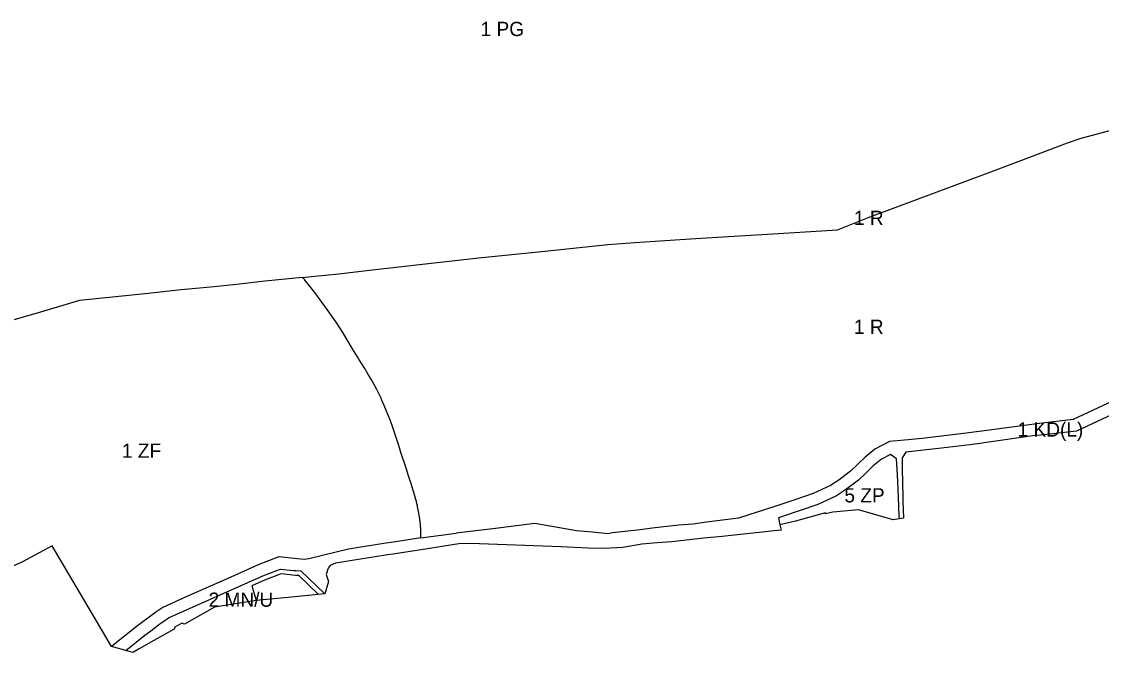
# Model space of a CAD drawing. Extents: x -286517 to -284367, y 35407 to 36486.
# Drawn here: x -286009 to -285100, y 35407 to 35938 of the extents above; entities that cross this region are included whole.
import ezdxf

# ---------------------------------------------------------------- set-up
doc = ezdxf.new("R2010")
doc.units = 0
for name, color, linetype in [('linie_rozgraniczajace', 7, 'Continuous'), ('linie_zabudowy_nieprzekraczalne', 7, 'Continuous'), ('oznaczenia_przeznaczen', 7, 'Continuous')]:
    doc.layers.add(name, color=color, linetype=linetype)

msp = doc.modelspace()

# ---------------------------------------------------------------- linework, layer by layer
at = {"layer": 'linie_rozgraniczajace'}
for p, q in [((-285772.1, 35722.75), (-285764.7, 35723.49)), ((-285672.47, 35503.54), (-285642.78, 35507.44))]:
    msp.add_line(p, q, dxfattribs=at)
for points in [[(-285764.7, 35723.49), (-285741.57, 35725.73), (-285715.72, 35728.86), (-285658.89, 35735.31), (-285621.32, 35739.63), (-285573.46, 35744.26), (-285515.27, 35750.49), (-285492.27, 35752.09), (-285441.45, 35755.6), (-285399.47, 35758.16), (-285371.51, 35759.76), (-285321.66, 35762.93), (-285296.42, 35772.95), (-285254.54, 35788.6), (-285197.18, 35810.16), (-285168.95, 35820.61), (-285128.18, 35836.27), (-285116.73, 35840.13), (-285060.82, 35855.07)], [(-285772.1, 35722.75), (-285804.01, 35719.56), (-285825.36, 35717.05), (-285846.68, 35714.99), (-285874.36, 35712.38), (-285902.1, 35709.3), (-285932.13, 35706.31), (-285959.96, 35703.43), (-285992.66, 35693.54), (-286021.94, 35685.16), (-286031.65, 35682.39)], [(-285672.47, 35503.54), (-285672.59, 35509.85), (-285672.95, 35514.75), (-285673.68, 35521.09), (-285674.72, 35527.12), (-285675.26, 35529.56), (-285675.49, 35530.6), (-285675.85, 35532.05), (-285676.33, 35533.99), (-285676.76, 35535.69), (-285677.61, 35538.8), (-285677.67, 35539.02), (-285679.81, 35546.07), (-285680.82, 35549.23), (-285681.53, 35551.43), (-285682.9, 35555.71), (-285684.97, 35562.13), (-285686.35, 35566.41), (-285687.89, 35571.22), (-285689.28, 35575.5), (-285691.19, 35581.36), (-285693.62, 35588.83), (-285696.05, 35596.3), (-285698.04, 35602.09), (-285701.36, 35610.08), (-285703.47, 35615.05), (-285705.62, 35620.11), (-285706, 35621), (-285707.39, 35624.07), (-285707.55, 35624.4), (-285708.96, 35627.23), (-285709.67, 35628.55), (-285713.15, 35635.07), (-285714.43, 35637.21), (-285717.13, 35641.69), (-285719.83, 35646.06), (-285724.7, 35653.92), (-285726.02, 35656.04), (-285730.11, 35662.65), (-285738.35, 35676.33), (-285743.26, 35684.15), (-285751.36, 35695.85), (-285761.83, 35710.13), (-285767.55, 35717.14), (-285770.26, 35720.58), (-285770.35, 35720.7), (-285772.1, 35722.75)], [(-285007.3, 35657.23), (-285123.28, 35603.1), (-285151.85, 35599.91), (-285200.22, 35593.46), (-285215.84, 35591.28), (-285250.46, 35587.29), (-285265.3, 35585.66), (-285278.05, 35584.62), (-285290.41, 35578.15), (-285298.47, 35571.48), (-285304.29, 35565.77), (-285310.72, 35559.57), (-285315.6, 35555.89), (-285320.66, 35552.08), (-285327.59, 35547.66), (-285342.17, 35540.82), (-285356.83, 35535.9), (-285374.6, 35529.96), (-285405.26, 35520.01), (-285414.23, 35518.91), (-285432.06, 35516.64), (-285443.44, 35515.15), (-285455.29, 35514.13), (-285465.42, 35512.98), (-285477.95, 35511.55), (-285487.83, 35510.37), (-285511.1, 35507.6), (-285515.26, 35506.97), (-285528.12, 35508.26), (-285541.4, 35509.47), (-285576.54, 35515.7), (-285609.77, 35511.46), (-285642.78, 35507.44)], [(-285038.41, 35631.83), (-285120.53, 35593.35), (-285150.63, 35589.98), (-285155.29, 35589.65), (-285198.44, 35583.61), (-285200, 35583.25), (-285201.51, 35582.91), (-285204.21, 35582.59), (-285210.29, 35581.87), (-285234.35, 35579.01), (-285264.34, 35575.7), (-285267.36, 35570.78), (-285267.31, 35562.03), (-285266.74, 35537.7), (-285266.71, 35534.18), (-285266.46, 35527.33), (-285266.33, 35520.07), (-285269.72, 35519.57), (-285275, 35518.8), (-285304.07, 35527.12), (-285325.73, 35525.21), (-285331.79, 35523.73), (-285331.99, 35524.52), (-285357.24, 35517.65), (-285370.29, 35514.52), (-285369.34, 35509.92), (-285375.26, 35509.28), (-285382.4, 35508.51), (-285413.7, 35505.12), (-285418.76, 35504.57), (-285434.62, 35503.21), (-285461.22, 35500.14), (-285473.65, 35499.32), (-285486.65, 35498.08), (-285502.52, 35495.5), (-285517.81, 35494.4), (-285532.11, 35494.94), (-285554.61, 35495.8), (-285630.65, 35498.69), (-285640.45, 35498.33), (-285666.86, 35494.25), (-285694.04, 35490.05), (-285702.22, 35488.79), (-285744.29, 35482.29), (-285748.82, 35480.33), (-285750.71, 35477.92), (-285752.39, 35472.6), (-285750.2, 35466.67), (-285753.42, 35456.22), (-285784.25, 35453.27), (-285811.3, 35450.71), (-285846.25, 35445), (-285871.63, 35430.82), (-285873.8, 35431.73), (-285879.55, 35428.23), (-285880.1, 35426.56), (-285897.36, 35417.1), (-285909.73, 35410.06), (-285914.97, 35407.03), (-285921.04, 35408.67), (-285933.05, 35411.9), (-285945.45, 35433.15), (-285980.21, 35491.87), (-285982.93, 35496.8), (-286008.44, 35482.9), (-286022.15, 35476.76)], [(-285269.72, 35519.57), (-285269.81, 35522), (-285270.33, 35537.5), (-285271.09, 35550.93), (-285271.35, 35556.17), (-285272.02, 35570.06), (-285277.11, 35573.82), (-285284.84, 35569.78), (-285291.77, 35564.04), (-285297.32, 35558.6), (-285304.22, 35551.95), (-285314.96, 35543.86), (-285322.76, 35538.89), (-285338.45, 35531.52), (-285368.87, 35521.31), (-285371.51, 35520.45), (-285370.29, 35514.52)], [(-285672.47, 35503.54), (-285695.56, 35499.93), (-285703.74, 35498.67), (-285733.51, 35494.07), (-285766.97, 35485.78), (-285770.81, 35485.4), (-285776.78, 35485.87), (-285792.16, 35487.46), (-285809.44, 35480.73), (-285829.94, 35471.61), (-285849.05, 35463.1), (-285869.44, 35454.02), (-285889.83, 35444.95), (-285895.74, 35440.89), (-285911.11, 35429.32), (-285933.05, 35411.9)], [(-285921.04, 35408.67), (-285905, 35421.41), (-285900.99, 35424.42), (-285896.2, 35428.03), (-285892.21, 35431.04), (-285889.9, 35432.77), (-285884.92, 35436.19), (-285805.59, 35471.5), (-285793.88, 35476.06), (-285790.79, 35477.26), (-285779.68, 35476.12), (-285777.69, 35475.91), (-285773.63, 35475.59), (-285753.42, 35456.22)]]:
    msp.add_lwpolyline(points, dxfattribs=at)
at = {"layer": 'linie_zabudowy_nieprzekraczalne'}
msp.add_lwpolyline([(-285758.67, 35455.72), (-285775.37, 35471.72), (-285778.05, 35471.93), (-285790.24, 35473.18), (-285804.05, 35467.81), (-285814.91, 35462.97), (-285811.3, 35450.71)], dxfattribs=at)

# ---------------------------------------------------------------- texts
at = {"layer": 'oznaczenia_przeznaczen'}
for s, p in [('1 PG', (-285622.25, 35926.05)), ('1 R', (-285307.96, 35766.95)), ('1 R', (-285307.96, 35675.21)), ('1 KD(L)', (-285170.18, 35588.8)), ('1 ZF', (-285924.16, 35570.89)), ('5 ZP', (-285315.98, 35533.33)), ('2 MN/U', (-285851.23, 35445.45))]:
    msp.add_text(s, height=12, dxfattribs=at).set_placement(p)

doc.saveas('drawing.dxf')
